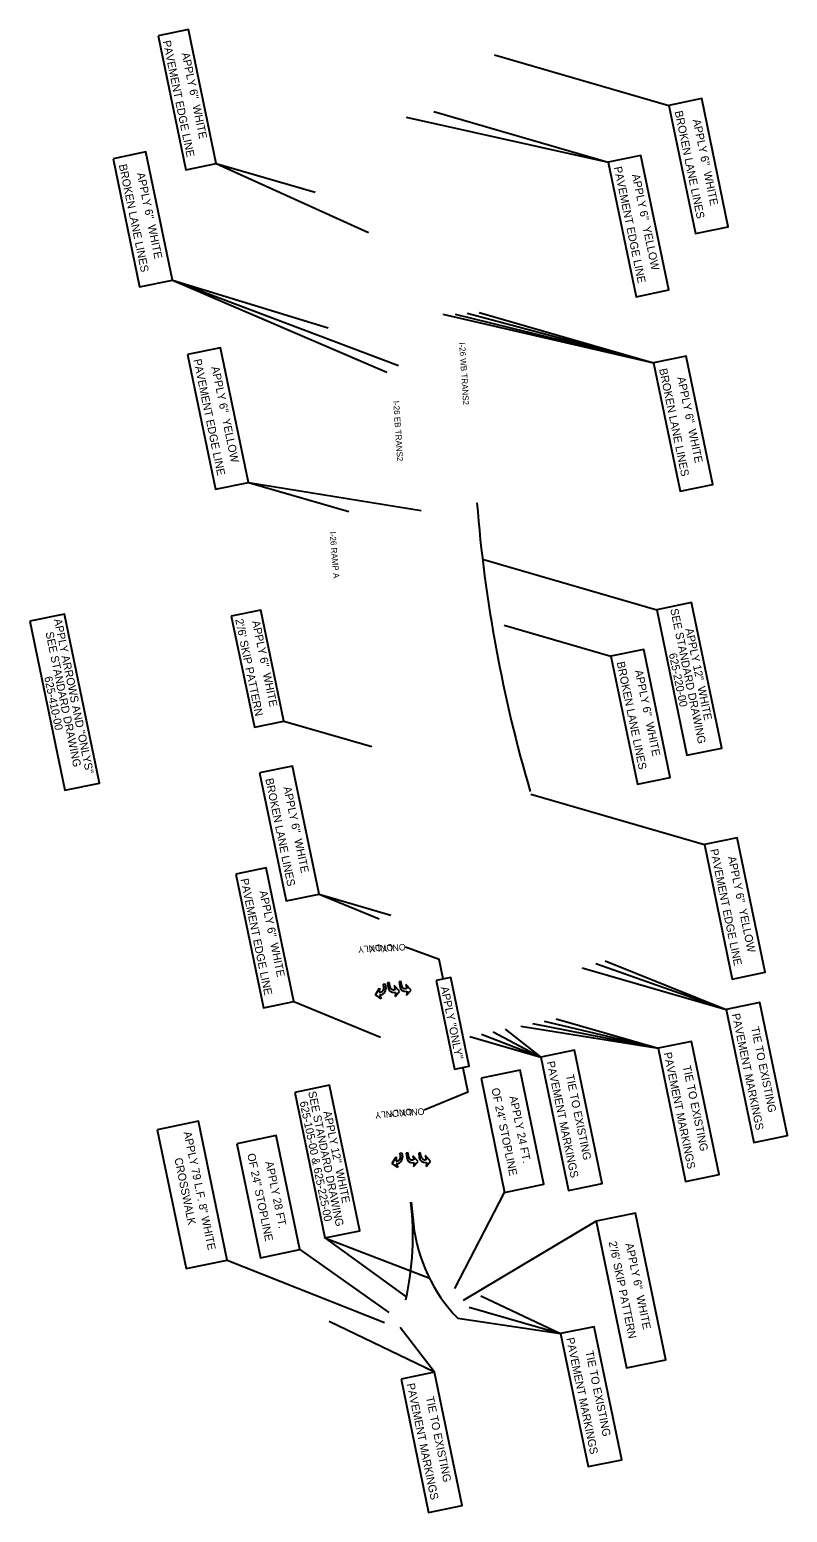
# Model space of a CAD drawing. Extents: x 1966013 to 1974896, y 789499 to 804826.
# Drawn here: x 1966013 to 1966770, y 789609 to 791091 of the extents above; entities that cross this region are included whole.
import ezdxf

# ---------------------------------------------------------------- set-up
doc = ezdxf.new("R2010")
doc.units = 0
for name, color, linetype in [('RD_EX_H2O_BlueLn', 7, 'Continuous'), ('RD_HC_Data_Tic_Rel', 7, 'Continuous'), ('RD_HC_TX_Rel_Sta50', 7, 'Continuous'), ('RD_PD_Final_Cl', 7, 'Continuous'), ('RD_PD_Final_LnLine', 7, 'Continuous'), ('RD_PD_MedBWall', 7, 'Continuous')]:
    doc.layers.add(name, color=color, linetype=linetype)

msp = doc.modelspace()

# ---------------------------------------------------------------- linework, layer by layer
at = {"layer": 'RD_EX_H2O_BlueLn'}
for p, q in [((1966477.7, 791066.2), (1966651.8, 791015.6)), ((1966417, 791009.4), (1966591.1, 790958.8)), ((1966389.3, 791003.7), (1966591.1, 790958.8)), ((1966199.7, 790957.4), (1966298.4, 790928.8)), ((1966199.7, 790957.4), (1966351.8, 790888.4)), ((1966155.9, 790841), (1966311.4, 790793.3)), ((1966155.9, 790841), (1966370.2, 790749)), ((1966155.9, 790841), (1966381.8, 790755.5)), ((1966426.1, 790806.9), (1966636.3, 790758.1)), ((1966438.4, 790806.9), (1966636.3, 790758.1)), ((1966450.3, 790807.9), (1966636.3, 790758.1)), ((1966462.2, 790808.7), (1966636.3, 790758.1)), ((1966231.8, 790638.8), (1966332, 790609.6)), ((1966231.8, 790638.8), (1966404.2, 790610.8)), ((1966465.6, 790562), (1966639.7, 790511.4)), ((1966487.2, 790496.1), (1966593.9, 790465.1)), ((1966267.2, 790400.1), (1966354.9, 790374.6)), ((1966514, 790327), (1966687.2, 790276.7)), ((1966302.3, 790227.2), (1966374, 790206.3)), ((1966302.3, 790227.2), (1966362.4, 790202.4)), ((1966565.1, 790153.6), (1966709, 790111.8)), ((1966578.9, 790157.7), (1966709, 790111.8)), ((1966588.1, 790160.4), (1966709, 790111.8)), ((1966277.3, 790119.7), (1966363.6, 790084.3)), ((1966488.2, 790092.1), (1966524, 790064.1)), ((1966503.8, 790095.3), (1966640.9, 790073.1)), ((1966515.6, 790097.8), (1966640.9, 790073.1)), ((1966527.3, 790100.2), (1966640.9, 790073.1)), ((1966539.1, 790102.6), (1966640.9, 790073.1)), ((1966452.9, 790084.8), (1966524, 790064.1)), ((1966464.7, 790087.2), (1966524, 790064.1)), ((1966476.4, 790089.6), (1966524, 790064.1)), ((1966437.8, 789832.9), (1966487.7, 789929.1)), ((1966579.1, 789900.3), (1966446.3, 789821.1)), ((1966308.2, 789883.5), (1966412, 789843.5)), ((1966308.2, 789883.5), (1966389.4, 789824.7)), ((1966283.1, 789871.8), (1966372, 789808.9)), ((1966210.6, 789861.4), (1966367.6, 789799)), ((1966463.9, 789825.5), (1966543.5, 789787.9)), ((1966452.4, 789814.3), (1966543.5, 789787.9)), ((1966417.7, 789749.2), (1966312.3, 789800.1)), ((1966417.7, 789749.2), (1966383.2, 789794)), ((1966440.9, 789803.2), (1966543.5, 789787.9))]:
    msp.add_line(p, q, dxfattribs=at)
for points in [[(1966141.5, 791085), (1966169.2, 790951.1), (1966199.7, 790957.4), (1966172, 791091.3)], [(1966651.8, 791015.6), (1966678.3, 790887.5), (1966711.1, 790894.3), (1966684.5, 791022.4)], [(1966096.6, 790962.3), (1966123.1, 790834.2), (1966155.9, 790841), (1966129.3, 790969.1)], [(1966591.1, 790958.8), (1966619, 790824.3), (1966651.8, 790831.1), (1966623.9, 790965.6)], [(1966171.1, 790766.5), (1966199, 790632), (1966231.8, 790638.8), (1966203.9, 790773.3)], [(1966636.3, 790758.1), (1966662.9, 790630.1), (1966695.7, 790636.8), (1966669.1, 790764.9)], [(1966013.3, 790499.9), (1966048.3, 790331), (1966083.1, 790338.2), (1966048.1, 790507.1)], [(1966214.7, 790504.9), (1966237.7, 790394), (1966267.2, 790400.1), (1966244.2, 790511)], [(1966639.7, 790511.4), (1966669.8, 790366), (1966704.6, 790373.2), (1966674.5, 790518.7)], [(1966593.9, 790465.1), (1966620.5, 790337), (1966653.2, 790343.8), (1966626.7, 790471.8)], [(1966242.9, 790348.5), (1966269.5, 790220.4), (1966302.3, 790227.2), (1966275.7, 790355.2)], [(1966687.2, 790276.7), (1966715, 790142.3), (1966747.8, 790149.1), (1966719.9, 790283.5)], [(1966219.1, 790247.3), (1966246.8, 790113.4), (1966277.3, 790119.7), (1966249.6, 790253.6)], [(1966419.2, 790140.9), (1966437.6, 790052.1), (1966452.2, 790055.2), (1966433.8, 790143.9)], [(1966709, 790111.8), (1966736.6, 789978.8), (1966770.1, 789985.8), (1966742.5, 790118.7)], [(1966640.9, 790073.1), (1966668.4, 789940.1), (1966701.9, 789947), (1966674.4, 790080)], [(1966524, 790064.1), (1966551.6, 789931.1), (1966585.1, 789938.1), (1966557.5, 790071.1)], [(1966464.1, 790043.1), (1966487.7, 789929.1), (1966526.9, 789937.2), (1966503.3, 790051.2)], [(1966278.1, 790028.9), (1966308.2, 789883.5), (1966343, 789890.7), (1966312.9, 790036.2)], [(1966140.8, 789991.6), (1966169.6, 789852.9), (1966210.6, 789861.4), (1966181.8, 790000.1)], [(1966220.3, 789977.7), (1966243.9, 789863.7), (1966283.1, 789871.8), (1966259.5, 789985.8)], [(1966579.1, 789900.3), (1966609.5, 789753.6), (1966648.7, 789761.7), (1966618.3, 789908.4)], [(1966543.5, 789787.9), (1966571.1, 789654.9), (1966604.6, 789661.8), (1966577, 789794.8)], [(1966384.2, 789742.2), (1966411.8, 789609.2), (1966445.3, 789616.2), (1966417.7, 789749.2)]]:
    msp.add_lwpolyline(points, close=True, dxfattribs=at)
for points in [[(1966426.4, 790142.6), (1966422.4, 790161.7), (1966388.6, 790174.2)], [(1966445.8, 790053.7), (1966450.8, 790029.3), (1966407.4, 790011.4)]]:
    msp.add_lwpolyline(points, dxfattribs=at)
at = {"layer": 'RD_HC_TX_Rel_Sta50'}
for p, q in [((1966366.6, 790137.2), (1966368.3, 790137.4)), ((1966366.6, 790137.2), (1966368.3, 790137.4)), ((1966367, 790133.7), (1966366.6, 790137.2)), ((1966366.6, 790137.2), (1966366.6, 790137.2)), ((1966367, 790133.7), (1966366.6, 790137.2)), ((1966366.6, 790137.2), (1966366.6, 790137.2)), ((1966368.3, 790137.4), (1966368.9, 790132.9)), ((1966368.3, 790137.4), (1966368.9, 790132.9)), ((1966372.6, 790138.6), (1966370.8, 790138.4)), ((1966372.6, 790138.6), (1966370.8, 790138.4)), ((1966370.8, 790138.4), (1966371.4, 790133.9)), ((1966370.8, 790138.4), (1966371.4, 790133.9)), ((1966373, 790135.2), (1966372.6, 790138.6)), ((1966372.6, 790138.6), (1966372.6, 790138.6)), ((1966373, 790135.2), (1966372.6, 790138.6)), ((1966372.6, 790138.6), (1966372.6, 790138.6)), ((1966382.6, 790130.1), (1966377.4, 790135.7)), ((1966377.4, 790135.7), (1966378.4, 790131.7)), ((1966382.6, 790130.1), (1966377.4, 790135.7)), ((1966377.4, 790135.7), (1966378.4, 790131.7)), ((1966384.2, 790139.8), (1966382.4, 790139.6)), ((1966384.2, 790139.8), (1966382.4, 790139.6)), ((1966382.4, 790139.6), (1966382.9, 790135.1)), ((1966382.4, 790139.6), (1966382.9, 790135.1)), ((1966384.6, 790136.4), (1966384.2, 790139.8)), ((1966384.2, 790139.8), (1966384.2, 790139.8)), ((1966384.6, 790136.4), (1966384.2, 790139.8)), ((1966384.2, 790139.8), (1966384.2, 790139.8)), ((1966394.2, 790131.3), (1966388.9, 790136.9)), ((1966388.9, 790136.9), (1966390, 790132.9)), ((1966394.2, 790131.3), (1966388.9, 790136.9)), ((1966388.9, 790136.9), (1966390, 790132.9)), ((1966358.8, 790126.6), (1966362.6, 790133.2)), ((1966358.8, 790126.6), (1966362.6, 790133.2)), ((1966364.4, 790122.5), (1966358.8, 790126.6)), ((1966364.4, 790122.5), (1966358.8, 790126.6)), ((1966362.6, 790133.2), (1966362.5, 790129.1)), ((1966362.6, 790133.2), (1966362.5, 790129.1)), ((1966362.5, 790129.1), (1966363.6, 790129.3)), ((1966362.5, 790129.1), (1966363.6, 790129.3)), ((1966363.9, 790126.4), (1966362.8, 790126.3)), ((1966363.9, 790126.4), (1966362.8, 790126.3)), ((1966362.8, 790126.3), (1966364.4, 790122.5)), ((1966362.8, 790126.3), (1966364.4, 790122.5)), ((1966378.4, 790131.7), (1966377.4, 790131.6)), ((1966378.4, 790131.7), (1966377.4, 790131.6)), ((1966377.7, 790128.8), (1966378.8, 790128.9)), ((1966377.7, 790128.8), (1966378.8, 790128.9)), ((1966378.2, 790124.9), (1966382.6, 790130.1)), ((1966378.2, 790124.9), (1966382.6, 790130.1)), ((1966378.8, 790128.9), (1966378.2, 790124.9)), ((1966378.8, 790128.9), (1966378.2, 790124.9)), ((1966390, 790132.9), (1966389, 790132.8)), ((1966390, 790132.9), (1966389, 790132.8)), ((1966389.3, 790130), (1966390.4, 790130.1)), ((1966389.3, 790130), (1966390.4, 790130.1)), ((1966389.8, 790126.1), (1966394.2, 790131.3)), ((1966389.8, 790126.1), (1966394.2, 790131.3)), ((1966390.4, 790130.1), (1966389.8, 790126.1)), ((1966390.4, 790130.1), (1966389.8, 790126.1)), ((1966375.5, 789957.9), (1966379.3, 789964.5)), ((1966375.5, 789957.9), (1966379.3, 789964.5)), ((1966381.1, 789953.8), (1966375.5, 789957.9)), ((1966381.1, 789953.8), (1966375.5, 789957.9)), ((1966379.3, 789964.5), (1966379.2, 789960.4)), ((1966379.3, 789964.5), (1966379.2, 789960.4)), ((1966379.2, 789960.4), (1966380.3, 789960.5)), ((1966379.2, 789960.4), (1966380.3, 789960.5)), ((1966380.6, 789957.7), (1966379.5, 789957.6)), ((1966380.6, 789957.7), (1966379.5, 789957.6)), ((1966379.5, 789957.6), (1966381.1, 789953.8)), ((1966379.5, 789957.6), (1966381.1, 789953.8)), ((1966383.3, 789968.4), (1966385, 789968.7)), ((1966383.3, 789968.4), (1966385, 789968.7)), ((1966383.7, 789965), (1966383.3, 789968.4)), ((1966383.3, 789968.4), (1966383.3, 789968.4)), ((1966383.7, 789965), (1966383.3, 789968.4)), ((1966383.3, 789968.4), (1966383.3, 789968.4)), ((1966385, 789968.7), (1966385.6, 789964.2)), ((1966385, 789968.7), (1966385.6, 789964.2)), ((1966391.2, 789968.5), (1966389.4, 789968.3)), ((1966391.2, 789968.5), (1966389.4, 789968.3)), ((1966389.4, 789968.3), (1966389.9, 789963.8)), ((1966389.4, 789968.3), (1966389.9, 789963.8)), ((1966391.6, 789965), (1966391.2, 789968.5)), ((1966391.2, 789968.5), (1966391.2, 789968.5)), ((1966391.6, 789965), (1966391.2, 789968.5)), ((1966391.2, 789968.5), (1966391.2, 789968.5)), ((1966401.2, 789960), (1966396, 789965.6)), ((1966396, 789965.6), (1966397, 789961.6)), ((1966401.2, 789960), (1966396, 789965.6)), ((1966396, 789965.6), (1966397, 789961.6)), ((1966397, 789961.6), (1966396, 789961.5)), ((1966397, 789961.6), (1966396, 789961.5)), ((1966396.3, 789958.7), (1966397.4, 789958.8)), ((1966396.3, 789958.7), (1966397.4, 789958.8)), ((1966396.8, 789954.8), (1966401.2, 789960)), ((1966396.8, 789954.8), (1966401.2, 789960)), ((1966397.4, 789958.8), (1966396.8, 789954.8)), ((1966397.4, 789958.8), (1966396.8, 789954.8)), ((1966403.6, 789968.7), (1966401.9, 789968.4)), ((1966403.6, 789968.7), (1966401.9, 789968.4)), ((1966401.9, 789968.4), (1966402.4, 789964)), ((1966401.9, 789968.4), (1966402.4, 789964)), ((1966404.1, 789965.2), (1966403.6, 789968.7)), ((1966403.6, 789968.7), (1966403.6, 789968.7)), ((1966404.1, 789965.2), (1966403.6, 789968.7)), ((1966403.6, 789968.7), (1966403.6, 789968.7)), ((1966413.7, 789960.2), (1966408.4, 789965.8)), ((1966408.4, 789965.8), (1966409.5, 789961.8)), ((1966413.7, 789960.2), (1966408.4, 789965.8)), ((1966408.4, 789965.8), (1966409.5, 789961.8)), ((1966409.5, 789961.8), (1966408.4, 789961.7)), ((1966409.5, 789961.8), (1966408.4, 789961.7)), ((1966408.8, 789958.9), (1966409.8, 789959)), ((1966408.8, 789958.9), (1966409.8, 789959)), ((1966409.2, 789955), (1966413.7, 789960.2)), ((1966409.2, 789955), (1966413.7, 789960.2)), ((1966409.8, 789959), (1966409.2, 789955)), ((1966409.8, 789959), (1966409.2, 789955))]:
    msp.add_line(p, q, dxfattribs=at)
for centre, radius, start, end in [((1966376.9, 790135.5), 3.92, 185.0848, 276.8476), ((1966376.9, 790135.5), 3.92, 185.0848, 276.8476), ((1966388.7, 790135.8), 5.82, 186.8094, 275.6519), ((1966388.7, 790135.8), 5.82, 186.8094, 275.6519), ((1966388.5, 790136.7), 3.92, 185.0848, 276.8476), ((1966388.5, 790136.7), 3.92, 185.0848, 276.8476), ((1966363.1, 790133.2), 3.92, 276.7956, 8.5585), ((1966363.1, 790133.2), 3.92, 276.7956, 8.5585), ((1966363.1, 790132.2), 5.82, 277.9913, 6.8339), ((1966363.1, 790132.2), 5.82, 277.9913, 6.8339), ((1966377.1, 790134.6), 5.82, 186.8094, 275.6519), ((1966377.1, 790134.6), 5.82, 186.8094, 275.6519), ((1966379.8, 789964.4), 3.92, 276.7956, 8.5585), ((1966379.8, 789964.4), 3.92, 276.7956, 8.5585), ((1966379.8, 789963.5), 5.82, 277.9913, 6.8339), ((1966379.8, 789963.5), 5.82, 277.9913, 6.8339), ((1966395.7, 789964.5), 5.82, 186.8094, 275.6519), ((1966395.7, 789964.5), 5.82, 186.8094, 275.6519), ((1966395.5, 789965.4), 3.92, 185.0848, 276.8476), ((1966395.5, 789965.4), 3.92, 185.0848, 276.8476), ((1966408.2, 789964.7), 5.82, 186.8094, 275.6519), ((1966408.2, 789964.7), 5.82, 186.8094, 275.6519), ((1966408, 789965.6), 3.92, 185.0848, 276.8476), ((1966408, 789965.6), 3.92, 185.0848, 276.8476)]:
    msp.add_arc(centre, radius, start, end, dxfattribs=at)
at = {"layer": 'RD_PD_Final_LnLine'}
msp.add_line((1966394.2, 789919.2), (1966396.6, 789897.3), dxfattribs=at)
for centre, radius, start, end in [((1967869.7, 790729.1), 1414, 184.4912, 196.4103), ((1966096, 789885.7), 300, 347.6827, 6.3991), ((1966556.9, 789915.3), 161.3, 186.3991, 223.9944)]:
    msp.add_arc(centre, radius, start, end, dxfattribs=at)

# ---------------------------------------------------------------- texts
at = {"layer": 'RD_EX_H2O_BlueLn'}
for s, height, rotation, p in [('PAVEMENT EDGE LINE', 8, 281.7118, (1966146.2, 791079.7)), ("APPLY 6''  WHITE", 8, 281.7118, (1966165, 791067.6)), ('BROKEN LANE LINES', 8, 281.7118, (1966657.5, 791009.4)), ("APPLY 6''  WHITE", 8, 281.7118, (1966675.5, 791001)), ('BROKEN LANE LINES', 8, 281.7118, (1966102.3, 790956)), ('PAVEMENT EDGE LINE', 8, 281.7118, (1966596.8, 790953.7)), ("APPLY 6''  WHITE", 8, 281.7118, (1966120.3, 790947.7)), ("APPLY 6''  YELLOW", 8, 281.7118, (1966614.7, 790946.2)), ('PAVEMENT EDGE LINE', 8, 281.7118, (1966176.8, 790761.3)), ("APPLY 6''  YELLOW", 8, 281.7118, (1966194.7, 790753.9)), ('BROKEN LANE LINES', 8, 281.7118, (1966642, 790751.9)), ("APPLY 6''  WHITE", 8, 281.7118, (1966660.1, 790743.5)), ('SEE STANDARD DRAWING', 8, 281.7118, (1966653.1, 790511.9)), ('APPLY ARROWS AND "ONLYS"', 8, 281.7118, (1966037.4, 790501.7)), ("2'/6' SKIP PATTERN", 7.999, 281.712, (1966218.6, 790501.6)), ("APPLY 6''  WHITE", 7.999, 281.712, (1966235.3, 790499.8)), ("APPLY 12''  WHITE", 8, 281.7118, (1966668.2, 790492.2)), ('SEE STANDARD DRAWING', 8, 281.7118, (1966029.1, 790488.6)), ('625-220-00', 8, 281.7118, (1966651.7, 790467.3)), ('BROKEN LANE LINES', 8, 281.7118, (1966599.6, 790458.8)), ("APPLY 6''  WHITE", 8, 281.7118, (1966617.7, 790450.5)), ('625-410-00 ', 8, 281.7118, (1966027.8, 790444)), ('BROKEN LANE LINES', 8, 281.7118, (1966248.6, 790342.2)), ("APPLY 6''  WHITE", 8, 281.7118, (1966266.7, 790333.9)), ('PAVEMENT EDGE LINE', 8, 281.7118, (1966692.9, 790271.6)), ("APPLY 6''  YELLOW", 8, 281.7118, (1966710.7, 790264.2)), ('PAVEMENT EDGE LINE', 8, 281.7118, (1966223.8, 790242)), ("APPLY 6''  WHITE", 8, 281.7118, (1966242.7, 790229.9)), ('APPLY "ONLY"', 7.999, 281.6981, (1966423.7, 790134)), ('PAVEMENT MARKINGS', 8, 281.7118, (1966714.7, 790107.1)), ('TIE TO EXISTING', 8, 281.7118, (1966733.7, 790093.8)), ('PAVEMENT MARKINGS', 8, 281.7118, (1966646.5, 790068.3)), ('PAVEMENT MARKINGS', 8, 281.7118, (1966529.7, 790059.4)), ('TIE TO EXISTING', 8, 281.7118, (1966548.8, 790046.2)), ('TIE TO EXISTING', 8, 281.7118, (1966665.6, 790055.1)), ('OF 24" STOPLINE', 7.999, 281.7118, (1966474.5, 790032.6)), ('625-105-00 & 625-225-00', 8, 281.7118, (1966282.9, 790019.4)), ('SEE STANDARD DRAWING', 8, 281.7118, (1966291.4, 790029.4)), ('APPLY 24 FT.', 7.999, 281.7118, (1966492.4, 790024.7)), ("APPLY 12''  WHITE", 8, 281.7118, (1966306.6, 790009.6)), ('APPLY 79 L.F. 8" WHITE', 8, 281.7117, (1966167, 789989.1)), ('CROSSWALK', 8, 281.7117, (1966157.8, 789962.8)), ('OF 24" STOPLINE', 7.999, 281.7118, (1966230.6, 789967.2)), ('APPLY 28 FT.', 7.999, 281.7118, (1966248.6, 789959.3)), ("2'/6' SKIP PATTERN", 7.999, 281.712, (1966591.6, 789879.4)), ("APPLY 6''  WHITE", 7.999, 281.712, (1966608.3, 789877.6)), ('PAVEMENT MARKINGS', 8, 281.7118, (1966549.2, 789783.1)), ('TIE TO EXISTING', 8, 281.7118, (1966568.3, 789769.9)), ('PAVEMENT MARKINGS', 8, 281.7118, (1966389.9, 789737.5)), ('TIE TO EXISTING', 8, 281.7118, (1966409, 789724.3))]:
    msp.add_text(s, height=height, rotation=rotation, dxfattribs=at).set_placement(p)
at = {"layer": 'RD_HC_Data_Tic_Rel'}
for p in [(1966364.7, 790177.1), (1966376.1, 790177.5), (1966388.5, 790177.7), (1966381.8, 790011.5), (1966395, 790013.1), (1966407.2, 790013.4)]:
    msp.add_text('ONLY', height=6.56, rotation=185.3528, dxfattribs=at).set_placement(p)
at = {"layer": 'RD_PD_Final_Cl'}
msp.add_text('I-26 RAMP A', height=6, rotation=274.7924, dxfattribs=at).set_placement((1966312.8, 790589.3))
at = {"layer": 'RD_PD_MedBWall'}
for s, p in [('I-26 WB TRANS2', (1966442.2, 790778.6)), ('I-26 EB TRANS2', (1966376.4, 790720.1))]:
    msp.add_text(s, height=6, rotation=273.7386, dxfattribs=at).set_placement(p)

doc.saveas('drawing.dxf')
